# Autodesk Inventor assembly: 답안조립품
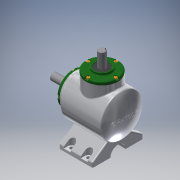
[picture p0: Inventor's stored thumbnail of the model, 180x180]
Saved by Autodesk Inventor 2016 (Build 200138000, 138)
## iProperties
Created: 2017-04
Part Number: 답안조립품
Material: 일반
Document SubType Name: Assembly
Designer: CAMTIC
Author: CAMTIC
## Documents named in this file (14)
- C:\Users\CAMTIC\Desktop\470407V1029\답안조립품.iam
- C:\Users\CAMTIC\Desktop\470407V1029\1-본체.ipt
- C:\Users\CAMTIC\Desktop\470407V1029\메인 베벨기어.ipt
- C:\Users\CAMTIC\Desktop\470407V1029\메인 축.ipt
- 메인 축.ipt
- C:\Users\CAMTIC\Desktop\470407V1029\베어링 6203.ipt
- C:\Users\CAMTIC\Desktop\470407V1029\볼트 M4.ipt
- C:\Users\CAMTIC\Desktop\470407V1029\서브 베벨기어.ipt
- C:\Users\CAMTIC\Desktop\470407V1029\서브 축.ipt
- 서브 축.ipt
- C:\Users\CAMTIC\Desktop\470407V1029\오일실 17 32 8.ipt
- C:\Users\CAMTIC\Desktop\470407V1029\커버.ipt
- C:\Users\CAMTIC\Desktop\470407V1029\키 4x4.ipt
- C:\Users\CAMTIC\Desktop\470407V1029\키 5x5.ipt
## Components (1 placed, 1 different names)
1. 1-본체:1
